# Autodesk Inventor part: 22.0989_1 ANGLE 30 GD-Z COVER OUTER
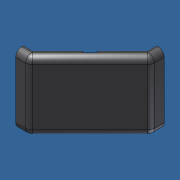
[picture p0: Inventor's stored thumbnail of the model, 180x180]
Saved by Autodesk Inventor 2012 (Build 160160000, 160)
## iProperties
Created: 2017-01
Part Number: 22.0989_1 ANGLE 30 GD-Z COVER OUTER
Material: ABS Plastic
Document SubType Name: Modeling
Designer: Admin
Density: 1.06 g/cm^3
Mass: 3.53131 g
Surface Area: 27.0421 cm^2
Volume: 3.33143 cm^3
Author: Admin
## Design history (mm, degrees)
feature "Base1"
body "Solid1"
